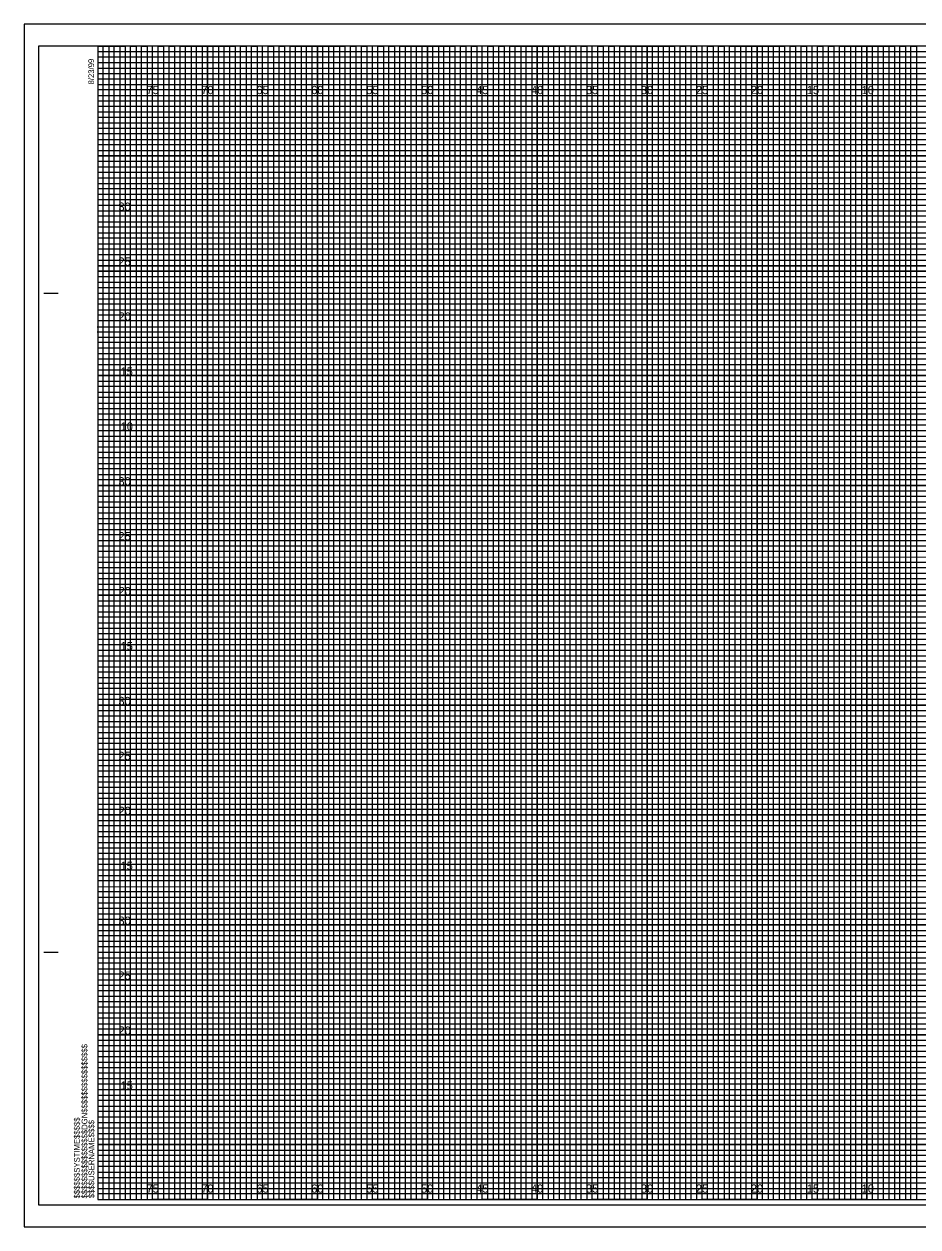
# Model space of a CAD drawing. Extents: x -7 to 162, y -3 to 107.
# Drawn here: x -6.7 to 74.6, y -2.5 to 107 of the extents above; entities that cross this region are included whole.
import ezdxf

# ---------------------------------------------------------------- set-up
doc = ezdxf.new("R2010")
doc.units = 0
for name, color, linetype in [('Exist Cross Section Cell', 7, 'Continuous'), ('Exist XS Center Line Elevation Label', 7, 'Continuous'), ('Exist XS Ground Line', 7, 'Continuous'), ('Prop CMT Pvmt Course 2', 7, 'Continuous'), ('Prop CMT Pvmt Course 3', 7, 'Continuous'), ('Prop CMT Pvmt Surface', 7, 'Continuous'), ('Prop CMT Pvmt Surface Shoulder', 7, 'Continuous'), ('Prop CMT Shld Paved Course 1', 7, 'Continuous'), ('Prop CMT Shld Paved Course 2', 7, 'Continuous'), ('Prop CMT Subgrade Earthwork', 7, 'Continuous'), ('Scratch_Level_0', 7, 'Continuous')]:
    doc.layers.add(name, color=color, linetype=linetype)

msp = doc.modelspace()

# ---------------------------------------------------------------- linework, layer by layer
at = {"layer": 'Exist XS Center Line Elevation Label'}
for points in [[(0, 105), (2.5, 105), (2.5, 0), (7.5, 0), (7.5, 105), (12.5, 105), (12.5, 0), (17.5, 0), (17.5, 105), (22.5, 105), (22.5, 0), (27.5, 0), (27.5, 105), (32.5, 105), (32.5, 0), (37.5, 0), (37.5, 105), (42.5, 105), (42.5, 0), (47.5, 0), (47.5, 105), (52.5, 105), (52.5, 0), (57.5, 0), (57.5, 105), (62.5, 105), (62.5, 0), (67.5, 0), (67.5, 105), (72.5, 105), (72.5, 0), (77.5, 0)], [(0, 102.5), (137.5, 102.5)], [(0, 92.5), (160, 92.5), (160, 97.5), (0, 97.5)], [(0, 82.5), (160, 82.5), (160, 87.5), (0, 87.5)], [(0, 72.5), (160, 72.5), (160, 77.5), (0, 77.5)], [(0, 62.5), (160, 62.5), (160, 67.5), (0, 67.5)], [(0, 52.5), (160, 52.5), (160, 57.5), (0, 57.5)], [(0, 42.5), (160, 42.5), (160, 47.5), (0, 47.5)], [(0, 32.5), (160, 32.5), (160, 37.5), (0, 37.5)], [(0, 22.5), (160, 22.5), (160, 27.5), (0, 27.5)], [(0, 12.5), (160, 12.5), (160, 17.5), (0, 17.5)], [(0, 2.5), (160, 2.5), (160, 7.5), (0, 7.5)]]:
    msp.add_lwpolyline(points, dxfattribs=at)
at = {"layer": 'Exist XS Ground Line'}
for p, q in [((5, 105), (0, 105)), ((5, 0), (5, 105)), ((15, 105), (10, 105)), ((10, 105), (10, 0)), ((15, 0), (15, 105)), ((25, 105), (20, 105)), ((20, 105), (20, 0)), ((25, 0), (25, 105)), ((35, 105), (30, 105)), ((30, 105), (30, 0)), ((35, 0), (35, 105)), ((45, 105), (40, 105)), ((40, 105), (40, 0)), ((45, 0), (45, 105)), ((55, 105), (50, 105)), ((50, 105), (50, 0)), ((55, 0), (55, 105)), ((65, 105), (60, 105)), ((60, 105), (60, 0)), ((65, 0), (65, 105)), ((75, 105), (70, 105)), ((70, 105), (70, 0)), ((10, 0), (5, 0)), ((20, 0), (15, 0)), ((30, 0), (25, 0)), ((40, 0), (35, 0)), ((50, 0), (45, 0)), ((60, 0), (55, 0)), ((70, 0), (65, 0))]:
    msp.add_line(p, q, dxfattribs=at)
for points in [[(0, 100), (160, 100), (160, 95), (0, 95)], [(0, 90), (160, 90), (160, 85), (0, 85)], [(0, 80), (160, 80), (160, 75), (0, 75)], [(0, 70), (160, 70), (160, 65), (0, 65)], [(0, 60), (160, 60), (160, 55), (0, 55)], [(0, 50), (160, 50), (160, 45), (0, 45)], [(0, 40), (160, 40), (160, 35), (0, 35)], [(0, 30), (160, 30), (160, 25), (0, 25)], [(0, 20), (160, 20), (160, 15), (0, 15)], [(0, 10), (160, 10), (160, 5), (0, 5)]]:
    msp.add_lwpolyline(points, dxfattribs=at)
at = {"layer": 'Prop CMT Pvmt Course 2'}
msp.add_lwpolyline([(-6.7, -2.5), (161.65, -2.5), (161.65, 107), (-6.7, 107)], close=True, dxfattribs=at)
at = {"layer": 'Prop CMT Pvmt Course 3'}
msp.add_lwpolyline([(-5.4, -0.5), (161.2, -0.5), (161.2, 105), (-5.4, 105)], close=True, dxfattribs=at)
at = {"layer": 'Prop CMT Pvmt Surface'}
for p, q in [((161.65, 107), (-6.7, 107)), ((-6.7, 107), (-6.7, -2.5)), ((-6.7, -2.5), (161.65, -2.5))]:
    msp.add_line(p, q, dxfattribs=at)
at = {"layer": 'Prop CMT Shld Paved Course 1'}
for p, q in [((-4.9, 82.5), (-3.65, 82.5)), ((-4.85, 82.5), (-3.6, 82.5)), ((-4.9, 22.5), (-3.65, 22.5)), ((-4.85, 22.5), (-3.6, 22.5)), ((0, 0), (0, 0)), ((0, 0), (0, 0)), ((0, 0), (0, 0)), ((0, 0), (0, 0)), ((0, 0), (0, 0)), ((0, 0), (0, 0)), ((0, 0), (0, 0))]:
    msp.add_line(p, q, dxfattribs=at)
msp.add_lwpolyline([(160, 105), (0, 105), (0, 0), (160, 0)], close=True, dxfattribs=at)
at = {"layer": 'Prop CMT Shld Paved Course 2'}
for points in [[(0, 0), (0.5, 0), (0.5, 105), (1, 105), (1, 0)], [(1, 0), (1.5, 0), (1.5, 105), (2, 105), (2, 0)], [(2.5, 0), (3, 0), (3, 105), (3.5, 105), (3.5, 0)], [(3.5, 0), (4, 0), (4, 105), (4.5, 105), (4.5, 0)], [(5, 0), (5.5, 0), (5.5, 105), (6, 105), (6, 0)], [(6, 0), (6.5, 0), (6.5, 105), (7, 105), (7, 0)], [(7.5, 0), (8, 0), (8, 105), (8.5, 105), (8.5, 0)], [(8.5, 0), (9, 0), (9, 105), (9.5, 105), (9.5, 0)], [(10, 0), (10.5, 0), (10.5, 105), (11, 105), (11, 0)], [(11, 0), (11.5, 0), (11.5, 105), (12, 105), (12, 0)], [(12.5, 0), (13, 0), (13, 105), (13.5, 105), (13.5, 0)], [(13.5, 0), (14, 0), (14, 105), (14.5, 105), (14.5, 0)], [(15, 0), (15.5, 0), (15.5, 105), (16, 105), (16, 0)], [(16, 0), (16.5, 0), (16.5, 105), (17, 105), (17, 0)], [(17.5, 0), (18, 0), (18, 105), (18.5, 105), (18.5, 0)], [(18.5, 0), (19, 0), (19, 105), (19.5, 105), (19.5, 0)], [(20, 0), (20.5, 0), (20.5, 105), (21, 105), (21, 0)], [(21, 0), (21.5, 0), (21.5, 105), (22, 105), (22, 0)], [(22.5, 0), (23, 0), (23, 105), (23.5, 105), (23.5, 0)], [(23.5, 0), (24, 0), (24, 105), (24.5, 105), (24.5, 0)], [(25, 0), (25.5, 0), (25.5, 105), (26, 105), (26, 0)], [(26, 0), (26.5, 0), (26.5, 105), (27, 105), (27, 0)], [(27.5, 0), (28, 0), (28, 105), (28.5, 105), (28.5, 0)], [(28.5, 0), (29, 0), (29, 105), (29.5, 105), (29.5, 0)], [(30, 0), (30.5, 0), (30.5, 105), (31, 105), (31, 0)], [(31, 0), (31.5, 0), (31.5, 105), (32, 105), (32, 0)], [(32.5, 0), (33, 0), (33, 105), (33.5, 105), (33.5, 0)], [(33.5, 0), (34, 0), (34, 105), (34.5, 105), (34.5, 0)], [(35, 0), (35.5, 0), (35.5, 105), (36, 105), (36, 0)], [(36, 0), (36.5, 0), (36.5, 105), (37, 105), (37, 0)], [(37.5, 0), (38, 0), (38, 105), (38.5, 105), (38.5, 0)], [(38.5, 0), (39, 0), (39, 105), (39.5, 105), (39.5, 0)], [(40, 0), (40.5, 0), (40.5, 105), (41, 105), (41, 0)], [(41, 0), (41.5, 0), (41.5, 105), (42, 105), (42, 0)], [(42.5, 0), (43, 0), (43, 105), (43.5, 105), (43.5, 0)], [(43.5, 0), (44, 0), (44, 105), (44.5, 105), (44.5, 0)], [(45, 0), (45.5, 0), (45.5, 105), (46, 105), (46, 0)], [(46, 0), (46.5, 0), (46.5, 105), (47, 105), (47, 0)], [(47.5, 0), (48, 0), (48, 105), (48.5, 105), (48.5, 0)], [(48.5, 0), (49, 0), (49, 105), (49.5, 105), (49.5, 0)], [(50, 0), (50.5, 0), (50.5, 105), (51, 105), (51, 0)], [(51, 0), (51.5, 0), (51.5, 105), (52, 105), (52, 0)], [(52.5, 0), (53, 0), (53, 105), (53.5, 105), (53.5, 0)], [(53.5, 0), (54, 0), (54, 105), (54.5, 105), (54.5, 0)], [(55, 0), (55.5, 0), (55.5, 105), (56, 105), (56, 0)], [(56, 0), (56.5, 0), (56.5, 105), (57, 105), (57, 0)], [(57.5, 0), (58, 0), (58, 105), (58.5, 105), (58.5, 0)], [(58.5, 0), (59, 0), (59, 105), (59.5, 105), (59.5, 0)], [(60, 0), (60.5, 0), (60.5, 105), (61, 105), (61, 0)], [(61, 0), (61.5, 0), (61.5, 105), (62, 105), (62, 0)], [(62.5, 0), (63, 0), (63, 105), (63.5, 105), (63.5, 0)], [(63.5, 0), (64, 0), (64, 105), (64.5, 105), (64.5, 0)], [(65, 0), (65.5, 0), (65.5, 105), (66, 105), (66, 0)], [(66, 0), (66.5, 0), (66.5, 105), (67, 105), (67, 0)], [(67.5, 0), (68, 0), (68, 105), (68.5, 105), (68.5, 0)], [(68.5, 0), (69, 0), (69, 105), (69.5, 105), (69.5, 0)], [(70, 0), (70.5, 0), (70.5, 105), (71, 105), (71, 0)], [(71, 0), (71.5, 0), (71.5, 105), (72, 105), (72, 0)], [(72.5, 0), (73, 0), (73, 105), (73.5, 105), (73.5, 0)], [(73.5, 0), (74, 0), (74, 105), (74.5, 105), (74.5, 0)]]:
    msp.add_lwpolyline(points, dxfattribs=at)
at = {"layer": 'Prop CMT Subgrade Earthwork'}
for p, q in [((5, 0), (5, 105)), ((10, 0), (10, 105)), ((15, 0), (15, 105)), ((20, 0), (20, 105)), ((25, 0), (25, 105)), ((30, 0), (30, 105)), ((35, 0), (35, 105)), ((40, 0), (40, 105)), ((45, 0), (45, 105)), ((50, 0), (50, 105)), ((55, 0), (55, 105)), ((60, 0), (60, 105)), ((65, 0), (65, 105)), ((70, 0), (70, 105)), ((0, 100), (160, 100)), ((0, 95), (160, 95)), ((0, 90), (160, 90)), ((0, 85), (160, 85)), ((0, 80), (160, 80)), ((0, 75), (160, 75)), ((0, 70), (160, 70)), ((0, 65), (160, 65)), ((0, 60), (160, 60)), ((0, 55), (160, 55)), ((0, 50), (160, 50)), ((0, 45), (160, 45)), ((0, 40), (160, 40)), ((0, 35), (160, 35)), ((0, 30), (160, 30)), ((0, 25), (160, 25)), ((0, 20), (160, 20)), ((0, 15), (160, 15)), ((0, 10), (160, 10)), ((0, 5), (160, 5))]:
    msp.add_line(p, q, dxfattribs=at)
at = {"layer": 'Scratch_Level_0'}
for p, q in [((0, 104.5), (130, 104.5)), ((130, 103.99), (0, 103.99)), ((0, 103.99), (0, 103.5)), ((0, 103.5), (130, 103.5)), ((130, 102.95), (0, 102.95)), ((0, 102.95), (0, 102)), ((0, 102), (160, 102))]:
    msp.add_line(p, q, dxfattribs=at)
for points in [[(0, 101.5), (135, 101.5), (160, 101.5), (160, 101), (0, 101)], [(0, 100.5), (160, 100.5), (160, 99.5), (0, 99.5)], [(0, 99), (160, 99), (160, 98.5), (0, 98.49)], [(0, 98), (160, 98), (160, 97), (0, 97)], [(0, 96.5), (160, 96.5), (160, 96), (0, 96)], [(0, 95.5), (160, 95.5), (160, 94.5), (0, 94.5)], [(0, 94), (160, 94), (160, 93.5), (0, 93.5)], [(0, 93), (160, 93), (160, 92), (0, 92)], [(0, 91.5), (160, 91.5), (160, 91), (0, 91)], [(0, 90.5), (160, 90.5), (160, 89.5), (0, 89.5)], [(0, 89), (160, 89), (160, 88.5), (0, 88.5)], [(0, 88), (160, 88), (160, 86.98), (160, 86.5), (160, 86), (0, 86)], [(0, 87), (160, 87), (160, 86.5), (0, 86.5)], [(0, 85.5), (160, 85.5), (160, 84.5), (0, 84.52)], [(0, 84.52), (160, 84.5), (160, 84), (0, 84)], [(0, 83.5), (160, 83.5), (160, 83), (0, 83)], [(0, 82), (160, 82), (160, 81.5), (0, 81.5)], [(0, 81), (160, 81), (160, 80.5), (0, 80.5)], [(-0.04, 79.45), (160, 79.45), (160, 78.94), (-0.04, 78.94)], [(0, 78.5), (160, 78.5), (160, 78), (0, 78)], [(0, 77), (160, 77), (160, 76.5), (0, 76.5)], [(0, 76), (160, 76), (160, 75.5), (0, 75.5)], [(0, 74.5), (160, 74.5), (160, 74), (0, 74)], [(0, 73.5), (160, 73.5), (160, 73), (0, 73)], [(0, 72), (160, 72), (160, 71.5), (0, 71.5)], [(0, 71), (160, 71), (160, 70.5), (0, 70.5)], [(0, 69.5), (160, 69.5), (160, 68.99), (0, 69)], [(0, 68.5), (160, 68.5), (160, 68), (0, 68)], [(0, 67), (160, 67), (160, 66.5), (0, 66.5)], [(0, 66), (160, 66), (160, 65.5), (0, 65.5)], [(0, 64.5), (160, 64.5), (160, 64), (0, 64)], [(0, 63.5), (160, 63.5), (160, 63), (0, 63)], [(0, 62), (160, 62), (160, 61.5), (0, 61.5)], [(0, 61), (160, 61), (160, 60.5), (0, 60.5)], [(0, 59.5), (160, 59.5), (160, 59), (0, 59)], [(0, 58.5), (160.03, 58.45), (160, 58), (0, 58)], [(0, 57), (160, 57), (160, 56.5), (0, 56.5)], [(0, 56), (160, 56), (160, 55.5), (0, 55.5)], [(0, 54.5), (160, 54.5), (160, 54), (0, 54)], [(0, 53.5), (160, 53.5), (160, 53), (0, 53)], [(0, 52), (160, 52), (160, 51.5), (0, 51.5)], [(0, 51), (160, 51), (160, 50.5), (0, 50.5)], [(0, 49.5), (160, 49.5), (160, 49), (0, 49)], [(0, 48.5), (160, 48.5), (160, 48), (0, 48)], [(0, 47), (160, 47), (160, 46.5), (0, 46.5)], [(0, 46), (160, 46), (160, 45.5), (0, 45.5)], [(0, 44.5), (160, 44.5), (160, 44), (0, 44)], [(0, 43.5), (160, 43.5), (160, 43), (0, 43)], [(0, 42), (160, 42), (160, 41.5), (0, 41.5)], [(0, 41), (160, 41), (160, 40.5), (0, 40.5)], [(0, 39.5), (160, 39.5), (160, 38.99), (0, 39)], [(0, 38.5), (160, 38.5), (160, 38), (0, 38)], [(0, 37), (160, 37), (160, 36.5), (0, 36.5)], [(0, 36), (160, 36), (160, 35.5), (0, 35.5)], [(0, 34.5), (160, 34.5), (160, 34), (0, 34)], [(0, 33.5), (160, 33.5), (160, 33), (0, 33)], [(0, 32), (160, 32), (160, 31.5), (0, 31.5)], [(0, 31), (160, 31), (160, 30.5), (0, 30.5)], [(0, 29.5), (160, 29.5), (160, 29), (0, 29)], [(0, 28.5), (160.03, 28.46), (160, 28), (0, 28)], [(0, 27), (160, 27), (160, 26.5), (0, 26.5)], [(0, 26), (160, 26), (160, 25.5), (0, 25.5)], [(0, 24.5), (160, 24.5), (160, 24), (0, 24)], [(0, 23.5), (160, 23.5), (160, 23), (0, 23)], [(0, 22), (160, 22), (160, 21.5), (0, 21.5)], [(0, 21), (160, 21), (160, 20.5), (0, 20.5)], [(0, 19.5), (160, 19.5), (160, 19), (0, 19)], [(0, 18.5), (160, 18.5), (160, 18), (0, 18)], [(0, 17), (160, 17), (160, 16.5), (0, 16.5)], [(0, 16), (160, 16), (160, 15.5), (0, 15.5)], [(0, 14.5), (160, 14.5), (160, 14), (0, 14)], [(0, 13.5), (160, 13.5), (160, 13), (0, 13)], [(0, 12), (160, 12), (160, 11.5), (0, 11.5)], [(0, 11), (160, 11), (160, 10.5), (0, 10.5)], [(0, 9.5), (160, 9.5), (160, 9), (0, 9)], [(0, 8.5), (160, 8.5), (160, 8), (0, 8)], [(0, 7), (160, 7), (160, 6.5), (0, 6.5)], [(0, 6), (160, 6), (160, 5.5), (0, 5.5)], [(0, 4.5), (160, 4.5), (160, 4), (0, 4)], [(0, 3.5), (160, 3.5), (160, 3), (0, 3)], [(0, 2), (160, 2), (160, 1.5), (0, 1.5)], [(0, 1), (160, 1), (160, 0.5), (0, 0.5)]]:
    msp.add_lwpolyline(points, dxfattribs=at)

# ---------------------------------------------------------------- texts
at = {"layer": 'Exist Cross Section Cell'}
for s, p in [('75', (4.44, 100.62)), ('70', (9.43, 100.62)), ('65', (14.44, 100.62)), ('60', (19.43, 100.62)), ('55', (24.44, 100.62)), ('50', (29.43, 100.62)), ('45', (34.44, 100.62)), ('40', (39.43, 100.62)), ('35', (44.44, 100.62)), ('30', (49.43, 100.62)), ('25', (54.44, 100.62)), ('20', (59.43, 100.62)), ('15', (64.53, 100.62)), ('10', (69.52, 100.62)), ('75', (4.44, 0.62)), ('70', (9.43, 0.62)), ('65', (14.44, 0.62)), ('60', (19.43, 0.62)), ('55', (24.44, 0.62)), ('50', (29.43, 0.62)), ('45', (34.44, 0.62)), ('40', (39.43, 0.62)), ('35', (44.44, 0.62)), ('30', (49.43, 0.62)), ('25', (54.44, 0.62)), ('20', (59.43, 0.62)), ('15', (64.53, 0.62)), ('10', (69.52, 0.62))]:
    msp.add_text(s, height=0.75, dxfattribs=at).set_placement(p)
at = {"layer": 'Prop CMT Pvmt Surface Shoulder'}
for s, p in [('30', (1.89, 90)), ('25', (1.89, 85)), ('20', (1.9, 80)), ('15', (2.08, 75)), ('10', (2.09, 70)), ('30', (1.89, 65)), ('25', (1.89, 60)), ('20', (1.9, 55)), ('15', (2.08, 50)), ('30', (1.89, 45)), ('25', (1.89, 40)), ('20', (1.9, 35)), ('15', (2.08, 30)), ('30', (1.89, 25)), ('25', (1.89, 20)), ('20', (1.9, 15)), ('15', (2.08, 10))]:
    msp.add_text(s, height=0.75, dxfattribs=at).set_placement(p)
at = {"layer": 'Prop CMT Shld Paved Course 1'}
for s, p in [('8/23/99', (-0.33, 101.5)), ('$$$$$$$$$$$$$$$$DGN$$$$$$$$$$$$$$$$', (-0.94, 0.09)), ('$$$$$$SYSTIME$$$$$', (-1.63, 0.09)), ('$$$$USERNAME$$$$', (-0.31, 0.12))]:
    msp.add_text(s, height=0.525, rotation=90, dxfattribs=at).set_placement(p)

doc.saveas('drawing.dxf')
